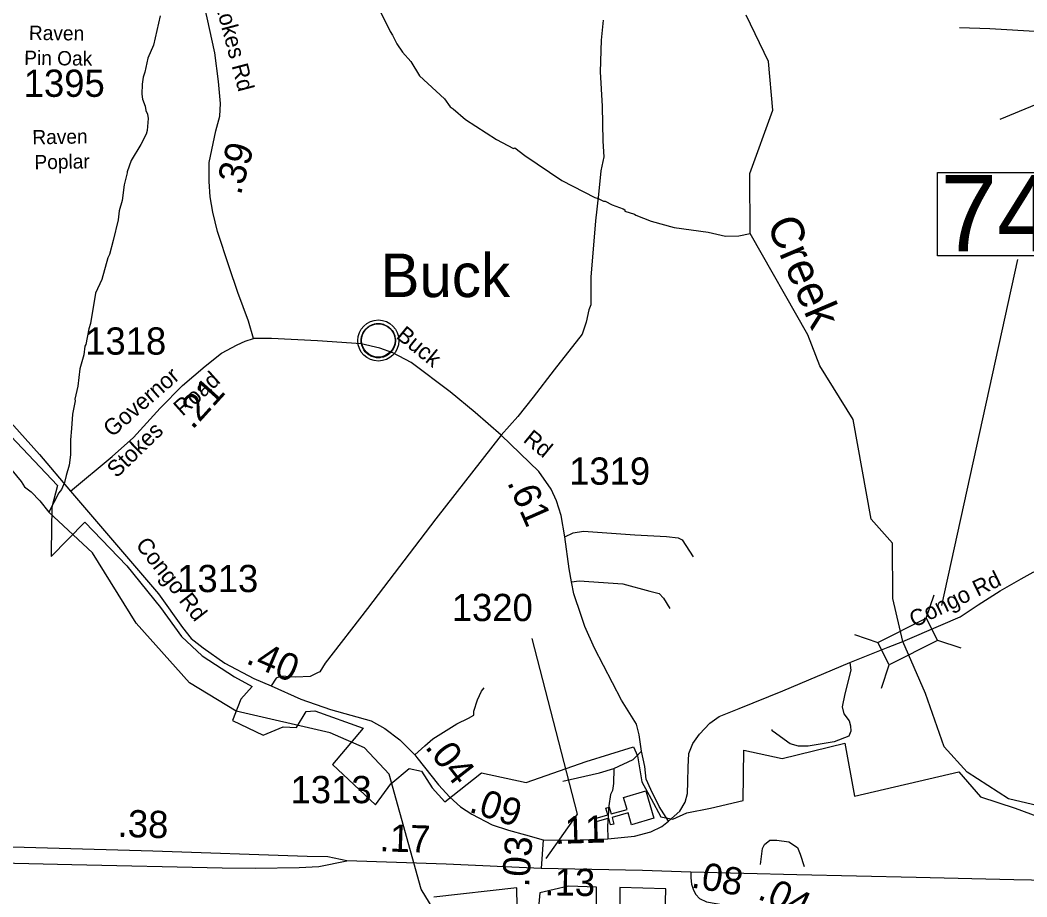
# Model space of a CAD drawing. Extents: x 1248089 to 1457196, y 820910 to 988753.
# Drawn here: x 1341654 to 1346272, y 880603 to 884627 of the extents above; entities that cross this region are included whole.
import ezdxf

# ---------------------------------------------------------------- set-up
doc = ezdxf.new("R2010")
doc.units = 0
for name, color, linetype in [('Exist Boundary Political City Limit New', 7, 'Continuous'), ('Exist Civil Demographics Community CELL', 7, 'Continuous'), ('Exist Civil Demographics Community Label', 7, 'Continuous'), ('Exist Cultural Church CELL', 7, 'Continuous'), ('Exist Hydrographic Creek Single Shore', 7, 'Continuous'), ('Exist Hydrographic Misc Water Feature', 7, 'Continuous'), ('Exist Road Non-System Type 51', 7, 'Continuous'), ('Exist Road Primary NC Structure Standard Bridge Number Label', 7, 'Continuous'), ('Exist Road Primary US Divided Attributed', 7, 'Continuous'), ('Exist Road Primary US Mileage Hundredths English Label', 7, 'Continuous'), ('Exist Road Primary US UnDivided 4 Lane Attributed', 7, 'Continuous'), ('Exist Road Secondary Structure Standard Bridge CELL', 7, 'Continuous'), ('Exist Road Secondary Structure Standard Bridge Number Label', 7, 'Continuous'), ('Exist Road Secondary Type 51 Attributed', 7, 'Continuous'), ('Exist Road Secondary Type 51 Label', 7, 'Continuous'), ('Map Preparation Boundary City Limit Buffer Line', 7, 'Continuous'), ('Prop GRAU CAT1 Cell', 7, 'Continuous'), ('Prop Lane Lines', 7, 'Continuous'), ('Scratch_Level_4', 7, 'Continuous')]:
    doc.layers.add(name, color=color, linetype=linetype)

msp = doc.modelspace()

# ---------------------------------------------------------------- linework, layer by layer
at = {"layer": 'Exist Boundary Political City Limit New'}
for points in [[(1341128, 883226.5), (1341825.7, 882492), (1341798.7, 882392.1), (1341796.1, 882187.7), (1341796.1, 882165.6), (1341951, 882322.3), (1342142.8, 882123), (1342297.7, 881931), (1342393.6, 881798.2), (1342489.5, 881709.6), (1342637, 881613.6), (1342718.1, 881569.4), (1342667.1, 881510.9), (1342627.7, 881412.6), (1342768.2, 881345.4), (1342860.8, 881383.8), (1342922.1, 881379.9), (1342965.5, 881453.8), (1343006.4, 881456.8), (1343227.2, 881377.8), (1343086.7, 881211.5), (1343284.7, 881026.1), (1343355, 881122), (1343438, 881192.4), (1343495.5, 881179.6), (1343544.2, 881103.7), (1343601.7, 881039.7), (1343770.2, 881173.2)], [(1343770.2, 881173.2), (1343974.6, 881128.4), (1344250.1, 881225.1), (1344467.3, 881292.3), (1344486.5, 881250.1), (1344506.1, 881132), (1344549.5, 881053.5), (1344593.7, 880969.9), (1344647.8, 880960), (1344711.7, 880989.5), (1344820.4, 881010.9), (1344970.5, 881046.1), (1344973.7, 881276.3), (1345149.4, 881237.9), (1345436.8, 881308.2), (1345481.5, 881065.3), (1345960.6, 881177.2), (1346059.7, 881062.1), (1346218.4, 881010.9), (1346512.3, 880902.3)], [(1343934.8, 880557.9), (1343933.2, 880644.2), (1343552.3, 880602.6)], [(1344298.6, 880535.5), (1344298.5, 880648.5), (1344169.1, 880651.7), (1344038.1, 880621.7), (1344032.2, 880554.7)], [(1344612.3, 880520.9), (1344616.8, 880640.9), (1344405.8, 880645.8), (1344405.6, 880537.1)]]:
    msp.add_lwpolyline(points, dxfattribs=at)
at = {"layer": 'Exist Civil Demographics Community CELL'}
msp.add_lwpolyline([(1343219.6, 883169.1), (1343220.6, 883174.6), (1343222.4, 883181.2), (1343225.3, 883188.4), (1343228.2, 883194.2), (1343231.6, 883199.9), (1343235.3, 883205), (1343239.3, 883209.4), (1343243.9, 883214), (1343249.4, 883218.6), (1343254.9, 883222.2), (1343259.7, 883225.1), (1343264.8, 883227.5), (1343270.2, 883229.8), (1343275.9, 883231.7), (1343280.2, 883232.8), (1343285.1, 883233.5), (1343289.2, 883234.3), (1343295.6, 883234.5), (1343300, 883234.4), (1343305.7, 883234.2), (1343310.6, 883233.4), (1343315.5, 883232.5), (1343320.5, 883231), (1343325.6, 883229.1), (1343332.3, 883226.2), (1343338.6, 883222.7), (1343343.6, 883219.1), (1343348.8, 883215.1), (1343352.1, 883212), (1343356.2, 883207.6), (1343360.1, 883202.9), (1343363.2, 883198.3), (1343366.3, 883193.3), (1343368.7, 883188.2), (1343370.8, 883183.1), (1343372.3, 883178.1), (1343373.6, 883173.5), (1343374.7, 883167.5), (1343375.3, 883162.8), (1343375.6, 883156.8), (1343375.4, 883151), (1343374.8, 883145.3), (1343373.9, 883139.8), (1343372.3, 883133.7), (1343370.4, 883127.8), (1343368.1, 883122.8), (1343364.9, 883116.8), (1343361.6, 883111.4), (1343358.2, 883106.8), (1343354, 883102), (1343348.7, 883097), (1343343.7, 883092.9), (1343338.7, 883089.5), (1343334.3, 883087), (1343327.5, 883083.7), (1343320.4, 883081), (1343314.4, 883079.6), (1343307.8, 883078.3), (1343303.4, 883077.8), (1343298.9, 883077.5), (1343293.3, 883077.5), (1343289, 883077.9), (1343283.4, 883078.7), (1343277.5, 883080), (1343272.9, 883081.3), (1343267.7, 883083.2), (1343263.1, 883085.2), (1343259.2, 883087.4), (1343252.4, 883091.5), (1343246.8, 883095.7), (1343241.9, 883100.2), (1343237.5, 883105.1), (1343234.3, 883109), (1343231.3, 883113.2), (1343227.2, 883120.3), (1343225.5, 883123.9), (1343223.8, 883127.9), (1343221.2, 883136.1), (1343219.6, 883143.1), (1343219, 883148.3), (1343218.6, 883154.6), (1343218.6, 883159.3), (1343219.1, 883165.8)], close=True, dxfattribs=at)
for centre, radius in [((1343297.3, 883156.6), 94.3), ((1343297, 883156.9), 76.7)]:
    msp.add_circle(centre, radius, dxfattribs=at)
at = {"layer": 'Exist Cultural Church CELL'}
msp.add_lwpolyline([(1344458.4, 880934.5), (1344442.6, 880989.2), (1344369.4, 880968.3), (1344378.2, 880937.5), (1344362.9, 880933.2), (1344354.1, 880963.9), (1344296.2, 880947.4), (1344291.8, 880962.8), (1344349.7, 880979.3), (1344340.9, 881010.1), (1344356.2, 881014.5), (1344365, 880983.7), (1344438.2, 881004.7), (1344422.5, 881060.1), (1344524.8, 881089.4), (1344560.7, 880963.8)], close=True, dxfattribs=at)
at = {"layer": 'Exist Hydrographic Creek Single Shore'}
for points in [[(1345657.8, 881973.1), (1345655.9, 882226.3), (1345557.9, 882336.7), (1345475.9, 882794.5), (1345322.8, 883040.6), (1345267.9, 883182.9), (1345002.8, 883647.8), (1345000.9, 883923.6), (1345106.8, 884213.7), (1345086.8, 884437.3), (1344983.9, 884649.4)], [(1345703.7, 881775.9), (1345657.8, 881973.1)], [(1346833.4, 880700.3), (1346790.8, 880745.3), (1346684.3, 880869.9), (1346492.7, 880981), (1346187.9, 881053.5), (1345998.9, 881175.4), (1345892.9, 881292.5), (1345807, 881537.2), (1345703.7, 881775.9)]]:
    msp.add_lwpolyline(points, dxfattribs=at)
at = {"layer": 'Exist Hydrographic Misc Water Feature'}
for points in [[(1343304.8, 884671.9), (1343350.7, 884574.8), (1343362.4, 884558.6), (1343381.4, 884518.1), (1343408.6, 884479.5), (1343445.6, 884436.7), (1343486.2, 884371.7), (1343600.5, 884266.5), (1343627.1, 884228.5), (1343640.8, 884220.1), (1343697.7, 884170.9), (1343839.7, 884079.7), (1343916.8, 884037.8), (1343922.9, 884041.7), (1343969.7, 884005.4), (1344139.6, 883890.8), (1344289.9, 883813.3), (1344305.8, 883809), (1344329.5, 883796.4), (1344337.5, 883796.3), (1344369.2, 883779.6), (1344420.7, 883760.4), (1344428.6, 883756.2), (1344428.4, 883750.1), (1344472.2, 883737.1), (1344478.4, 883732), (1344549.5, 883704.4), (1344654.8, 883675), (1344810.3, 883653.5), (1344890, 883635.6), (1344951.3, 883636.8), (1345002.8, 883647.8)], [(1342296.3, 884646.8), (1342265.2, 884511.6), (1342239.9, 884452.1), (1342226.5, 884388.5), (1342218, 884364.7), (1342213.2, 884332.8), (1342212.2, 884286.8), (1342215.8, 884264.7), (1342227.1, 884232.4), (1342230.6, 884212.4), (1342238.3, 884196.2), (1342241.9, 884176.1), (1342236.5, 884120.3), (1342232.2, 884104.4), (1342207.2, 884056.9), (1342163.2, 883982.6), (1342144.4, 883930.4), (1342145.6, 883925.7), (1342131, 883870.6), (1342121.5, 883798.8), (1342108.4, 883751.2), (1342103.5, 883711.3), (1342081.4, 883615.8), (1342064, 883552.2), (1342055.7, 883536.4), (1342029.4, 883437), (1342000, 883373.7), (1341976.9, 883234.2), (1341968.4, 883210.3), (1341954.8, 883138.7), (1341950.7, 883130.8), (1341945.8, 883090.9), (1341928.3, 883027.3), (1341918.6, 882947.6), (1341905.3, 882887.8), (1341906.4, 882880.5), (1341894.6, 882818.6), (1341888.9, 882753.3), (1341885.1, 882700.3), (1341885.6, 882632.3), (1341878.5, 882584.4), (1341864.9, 882537.5), (1341856.8, 882505), (1341844.1, 882473.2), (1341831.8, 882457.5), (1341785.1, 882369.3)], [(1341594.6, 882586.9), (1341658.9, 882509.5), (1341674.3, 882485.1), (1341703.8, 882462.4), (1341744.9, 882421.5), (1341785.1, 882369.3)], [(1345768, 875592.7), (1345866, 876240.8), (1345930, 876498.8), (1346022, 877261.8), (1345951.9, 877516.1), (1345878.9, 877593), (1345581.9, 877750), (1345426, 877877.9), (1345097, 878436.1), (1344993.9, 878677.7), (1344437.9, 879201), (1344315.9, 879334.8), (1344183.9, 879747.8), (1344062.9, 879940.6), (1343590.9, 880478.7), (1343493.9, 880638.2), (1343346.8, 881166.3), (1343233.9, 881286.9), (1343075.9, 881355.7), (1342644.8, 881456.3), (1342430.9, 881585.3), (1342186.9, 881859.4), (1341985.8, 882181.8), (1341785.1, 882369.3)]]:
    msp.add_lwpolyline(points, dxfattribs=at)
at = {"layer": 'Exist Road Non-System Type 51'}
msp.add_line((1344623.9, 880961.9), (1344623.9, 880959.9), dxfattribs=at)
for points in [[(1344329.2, 884627.2), (1344319.7, 884534.9), (1344315, 884390.5), (1344324.5, 884231.9), (1344326.7, 884072.3), (1344331.5, 883999), (1344317.3, 883935.1), (1344307.8, 883826.2), (1344293.6, 883705.5), (1344272.4, 883447.5), (1344272.4, 883320.9), (1344263, 883297.3), (1344251.1, 883240.5), (1344232.2, 883186), (1344104.5, 883022.7), (1344007.5, 882897.3), (1343936.6, 882807.4), (1343860.9, 882722.2)], [(1346334.3, 884572.7), (1346102.5, 884586.9), (1345963, 884591.6)], [(1346149.8, 884172.7), (1346379.2, 884267.4), (1346433.6, 884276.9), (1346525.9, 884286.3), (1346613.4, 884286.3), (1346707, 884274.2)], [(1343860.9, 882722.2), (1343561.2, 882337.9), (1343246.7, 881926.1), (1343053.2, 881676.1), (1343029.5, 881635.9), (1343017.7, 881631.1), (1342984.6, 881614.6), (1342918.4, 881612.2), (1342849.8, 881616.9), (1342828.5, 881607.5), (1342804.8, 881572)], [(1344152.7, 882256.1), (1344191, 882273.4), (1344238.1, 882281.2), (1344473.7, 882265.5), (1344619, 882257.7), (1344672.1, 882251.8), (1344691.7, 882241.9), (1344740.8, 882163.3)], [(1344183.1, 882049.4), (1344218.5, 882053.3), (1344418.7, 882039.5), (1344542.5, 882006.1), (1344585.7, 881996.3), (1344605.3, 881974.7), (1344634.7, 881927.5)], [(1345460.8, 881678.5), (1345464.7, 881643.1), (1345437.2, 881535), (1345425.5, 881476.1), (1345433.3, 881442.7), (1345456.9, 881411.2), (1345462.8, 881387.6), (1345464.7, 881364.1), (1345454.9, 881340.5), (1345388.1, 881314.9), (1345268.4, 881295.3), (1345225.2, 881295.3), (1345185.9, 881305.1), (1345158.4, 881324.8), (1345119.1, 881354.2), (1345103.4, 881366), (1345103.7, 881371.2)], [(1343464.4, 881255.8), (1343510.1, 881295.9), (1343547.4, 881329.3), (1343657.3, 881398.1), (1343710.4, 881423.6), (1343735.9, 881437.4), (1343735.9, 881455.1), (1343751.6, 881508.1), (1343771.2, 881547.4), (1343783, 881563.1)], [(1344378, 881191.7), (1344466.4, 881233), (1344504.5, 881272.7)], [(1344144.3, 881134.8), (1344311.2, 881172.1), (1344378, 881191.7)], [(1344378, 881191.7), (1344376, 881123), (1344372.1, 881091.5), (1344362.3, 881073.8), (1344354.4, 881020.8), (1344348.6, 880928.4), (1344350.5, 880869)], [(1345049.9, 880751.8), (1345059.4, 880825.1), (1345068.8, 880844.1)], [(1345068.8, 880844.1), (1345092.5, 880863), (1345125.6, 880863), (1345180, 880855.9), (1345220.2, 880829.9), (1345232, 880799.1), (1345250.9, 880742.3)]]:
    msp.add_lwpolyline(points, dxfattribs=at)
at = {"layer": 'Exist Road Primary NC Structure Standard Bridge Number Label'}
msp.add_line((1345881.7, 881941.2), (1346231.6, 883528.2), dxfattribs=at)
at = {"layer": 'Exist Road Primary US Divided Attributed'}
for points in [[(1343152.7, 880768.4), (1343065.9, 880786.7), (1342970.6, 880789.2), (1342262.1, 880812.7), (1341348.7, 880838.4), (1341168, 880836.1)], [(1341180, 880768.1), (1341518.8, 880762.7), (1341627.5, 880757.3), (1341891.1, 880751.8), (1342580, 880736.9), (1342733.6, 880735.5), (1342933.3, 880738.2), (1343024.9, 880743.3), (1343152.7, 880768.4)]]:
    msp.add_lwpolyline(points, dxfattribs=at)
at = {"layer": 'Exist Road Primary US UnDivided 4 Lane Attributed'}
for points in [[(1344043.6, 880733.6), (1343608.1, 880753.6), (1343152.7, 880768.4)], [(1344730.4, 880716), (1344509.3, 880724.9), (1344043.6, 880733.6)], [(1348210.7, 880640.1), (1347499.5, 880656.2), (1346855.7, 880668.8), (1346211.8, 880681.7), (1345764.7, 880691.7), (1345217.5, 880704.3), (1344730.4, 880716)]]:
    msp.add_lwpolyline(points, dxfattribs=at)
at = {"layer": 'Exist Road Secondary Structure Standard Bridge CELL'}
for p, q in [((1345810.9, 881882.3), (1345846.4, 881989.8)), ((1345481.8, 881806.9), (1345589.2, 881771.4)), ((1345861.8, 881781.2), (1345969.2, 881745.7)), ((1345605.8, 881560.5), (1345641.3, 881667.9))]:
    msp.add_line(p, q, dxfattribs=at)
msp.add_lwpolyline([(1345589.2, 881771.4), (1345810.7, 881882.8), (1345862.7, 881779.4), (1345641.3, 881667.9)], close=True, dxfattribs=at)
at = {"layer": 'Exist Road Secondary Structure Standard Bridge Number Label'}
msp.add_lwpolyline([(1345862.9, 883928.2), (1346507, 883928.2), (1346507, 883545.9), (1345862.9, 883545.9)], close=True, dxfattribs=at)
at = {"layer": 'Exist Road Secondary Type 51 Attributed'}
for points in [[(1342724, 883166.5), (1342701.6, 883246.2), (1342652.4, 883377.6), (1342612.6, 883494.9), (1342558.7, 883656.7), (1342537.6, 883745.9), (1342525.8, 883816.2), (1342521.2, 883886.6), (1342521.2, 883973.4), (1342551.6, 884118.8), (1342570.4, 884186), (1342572.7, 884244.7), (1342563.4, 884345.5), (1342547, 884476.9), (1342511.8, 884637.8), (1342465, 884839.5), (1342420.4, 884947.4), (1342375.9, 885050.6), (1342335.1, 885116), (1342311.1, 885154.7)], [(1340855.3, 883520.2), (1340941.3, 883446.1), (1341042.2, 883350.4), (1341225.8, 883175.3), (1341356.4, 883048), (1341477.7, 882928.7), (1341584.8, 882810.1), (1341742.6, 882633.9), (1341885.5, 882465.1)], [(1341885.5, 882465.1), (1342076.4, 882624.2), (1342174.5, 882711.8), (1342296.1, 882846.3), (1342398.5, 882950.9), (1342503.1, 883038.5), (1342577.8, 883098.3), (1342650.3, 883136.7), (1342686.6, 883153.8), (1342724, 883166.5)], [(1344627.8, 880951), (1344585.6, 881017.3), (1344547.2, 881096.4), (1344525.8, 881143.3), (1344519.4, 881201), (1344504.5, 881272.7), (1344493.9, 881347.4), (1344481.1, 881396.5), (1344412.8, 881505.4), (1344289, 881744.6), (1344244.5, 881843.9), (1344227.4, 881895.2), (1344193.3, 881993.4), (1344183.1, 882049.4), (1344171.9, 882108.7), (1344152.7, 882256.1), (1344135.7, 882354.3), (1344114.3, 882420.5), (1344090.8, 882473.9), (1344034.1, 882555.8), (1343860.9, 882722.2), (1343741.8, 882827), (1343626.6, 882921), (1343447.3, 883055.5), (1343364.1, 883100.3), (1343304.4, 883121.7), (1343219, 883140.9), (1343018.5, 883155.9), (1342807.2, 883166.5), (1342724, 883166.5)], [(1345703.7, 881775.9), (1345878, 881850.1), (1345966.3, 881888.1), (1346048.6, 881943.4), (1346149.2, 882008.5), (1346246.1, 882062.5), (1346301.3, 882093.2), (1346389.7, 882119), (1346519.8, 882142.3), (1346674.8, 882179.9), (1346786.5, 882215.5), (1346870, 882251.2), (1346965.7, 882299.1), (1347084.7, 882372.7), (1347242, 882485.7)], [(1341885.5, 882465.1), (1342288.3, 881993.9), (1342399.4, 881840.1), (1342437.8, 881789.4), (1342493.6, 881745.8), (1342593, 881676), (1342725.5, 881606.2), (1342804.8, 881572), (1342941.7, 881510.2), (1343077.7, 881463.1), (1343264.3, 881410.8), (1343326.6, 881376.3), (1343396.1, 881323.6), (1343464.4, 881255.8), (1343474.2, 881243.3), (1343509.7, 881198.3), (1343572.5, 881118), (1343624.8, 881060.4)], [(1344627.8, 880951), (1344680.2, 880996.7), (1344704.8, 881037.2), (1344715.8, 881077.7), (1344717, 881130.5), (1344718.3, 881198.1), (1344722, 881261.9), (1344740.4, 881307.4), (1344771, 881350.4), (1344817.7, 881400.7), (1344860.4, 881430.8), (1344952.5, 881467.6), (1345152.5, 881548.8), (1345460.8, 881678.5), (1345635.7, 881748.6), (1345703.7, 881775.9)], [(1343624.8, 881060.4), (1343673.6, 881016.8), (1343725.9, 880983.6), (1343819.3, 880933.7), (1343894.3, 880909.3), (1343972.8, 880888.3), (1344053, 880865.6)], [(1344053, 880865.6), (1344179.6, 880863.8), (1344350.5, 880869), (1344472.6, 880881.2), (1344547.5, 880902.2), (1344598.1, 880926.6), (1344627.8, 880951)], [(1344053, 880865.6), (1344043.6, 880733.6)], [(1344730.4, 880716), (1344730.4, 880691.1), (1344734.1, 880661), (1344742.9, 880634.7), (1344753.5, 880614), (1344770.4, 880596.5), (1344803, 880580.8), (1344882.5, 880567.2), (1345026.2, 880543.7), (1345062.7, 880534.9), (1345106.7, 880522.3), (1345143.2, 880507.2), (1345211.2, 880473.7), (1345235.3, 880456.6)]]:
    msp.add_lwpolyline(points, dxfattribs=at)
at = {"layer": 'Map Preparation Boundary City Limit Buffer Line'}
for points in [[(1341128, 883226.5), (1341825.7, 882492), (1341798.7, 882392.1), (1341796.1, 882187.7), (1341796.1, 882165.6), (1341951, 882322.3), (1342142.8, 882123), (1342297.7, 881931), (1342393.6, 881798.2), (1342489.5, 881709.6), (1342637, 881613.6), (1342718.1, 881569.4), (1342667.1, 881510.9), (1342627.7, 881412.6), (1342768.2, 881345.4), (1342860.8, 881383.8), (1342922.1, 881379.9), (1342965.5, 881453.8), (1343006.4, 881456.8), (1343227.2, 881377.8), (1343086.7, 881211.5), (1343284.7, 881026.1), (1343355, 881122), (1343438, 881192.4), (1343495.5, 881179.6), (1343544.2, 881103.7), (1343601.7, 881039.7), (1343770.2, 881173.2)], [(1343770.2, 881173.2), (1343974.6, 881128.4), (1344250.1, 881225.1), (1344467.3, 881292.3), (1344486.5, 881250.1), (1344506.1, 881132), (1344549.5, 881053.5), (1344593.7, 880969.9), (1344647.8, 880960), (1344711.7, 880989.5), (1344820.4, 881010.9), (1344970.5, 881046.1), (1344973.7, 881276.3), (1345149.4, 881237.9), (1345436.8, 881308.2), (1345481.5, 881065.3), (1345960.6, 881177.2), (1346059.7, 881062.1), (1346218.4, 881010.9), (1346512.3, 880902.3)], [(1343934.8, 880557.9), (1343933.2, 880644.2), (1343552.3, 880602.6)], [(1344298.6, 880535.5), (1344298.5, 880648.5), (1344169.1, 880651.7), (1344038.1, 880621.7), (1344032.2, 880554.7)], [(1344612.3, 880520.9), (1344616.8, 880640.9), (1344405.8, 880645.8), (1344405.6, 880537.1)]]:
    msp.add_lwpolyline(points, dxfattribs=at)
at = {"layer": 'Prop Lane Lines'}
msp.add_lwpolyline([(1344066.5, 880779.2), (1344211.6, 880982.3), (1344002.7, 881789)], dxfattribs=at)

# ---------------------------------------------------------------- texts
at = {"layer": 'Exist Civil Demographics Community Label'}
msp.add_text('Buck', height=200, dxfattribs=at).set_placement((1343307.4, 883356))
at = {"layer": 'Exist Road Primary US Mileage Hundredths English Label'}
for s, rotation, p in [('.38', 358.1057, (1342099.8, 880879.4)), ('.17', 358.1357, (1343301.6, 880812.8)), ('.13', 358.9293, (1344058.4, 880610.8))]:
    msp.add_text(s, height=125, rotation=rotation, dxfattribs=at).set_placement(p)
at = {"layer": 'Exist Road Secondary Structure Standard Bridge Number Label'}
msp.add_text('74', height=350, dxfattribs=at).set_placement((1345875.4, 883565.7))
at = {"layer": 'Exist Road Secondary Type 51 Label'}
for s, height, rotation, p in [('Governor Stokes Rd', 75, 284.8292, (1342423.8, 885172.2)), ('Raven', 65.62, 359.3359, (1341693.8, 884536.3)), (' Pin Oak', 65.62, 359.3359, (1341647.9, 884422)), ('Raven ', 65.62, 1.027, (1341710.4, 884056.8)), ('Poplar', 65.62, 1.027, (1341720.1, 883942.2)), ('Buck                   Rd', 75, 320.7671, (1343374.6, 883170.9)), ('Governor', 75, 40.9406, (1342075.4, 882709.9)), ('Road', 75, 41.8716, (1342399, 882806.1)), ('Stokes', 75, 44.1453, (1342096.3, 882522.6)), ('Congo Rd', 75, 307.9495, (1342180.5, 882217.5)), ('Congo Rd', 75, 26.0724, (1345755.9, 881837.4))]:
    msp.add_text(s, height=height, rotation=rotation, dxfattribs=at).set_placement(p)
at = {"layer": 'Prop GRAU CAT1 Cell'}
for s, rotation, p in [('.39', 74.3972, (1342665.3, 883820.3)), ('.21', 47.8853, (1342444.6, 882743.9)), ('.61', 293.7326, (1343886.5, 882505.7)), ('.40', 336.6544, (1342684.8, 881677.4)), ('.04', 308.0257, (1343507.5, 881290.4)), ('.09', 341.9527, (1343708, 880994.9)), ('.11', 1.7548, (1344108, 880846)), ('.03', 85.9139, (1343988, 880646)), ('.08', 350.3079, (1344728.4, 880647.1)), ('.04', 334.486, (1345031.8, 880597))]:
    msp.add_text(s, height=125, rotation=rotation, dxfattribs=at).set_placement(p)
at = {"layer": 'Prop Lane Lines'}
for s, p in [('1395', (1341670.3, 884275)), ('1318', (1341952.2, 883091.9)), ('1319', (1344172.4, 882494.9)), ('1313', (1342374.5, 882001.9)), ('1320', (1343634, 881869)), ('1313', (1342894.5, 881033.2))]:
    msp.add_text(s, height=125, dxfattribs=at).set_placement(p)
at = {"layer": 'Scratch_Level_4'}
msp.add_text('Creek', height=150, rotation=293.0582, dxfattribs=at).set_placement((1345077.2, 883691.9))

doc.saveas('drawing.dxf')
